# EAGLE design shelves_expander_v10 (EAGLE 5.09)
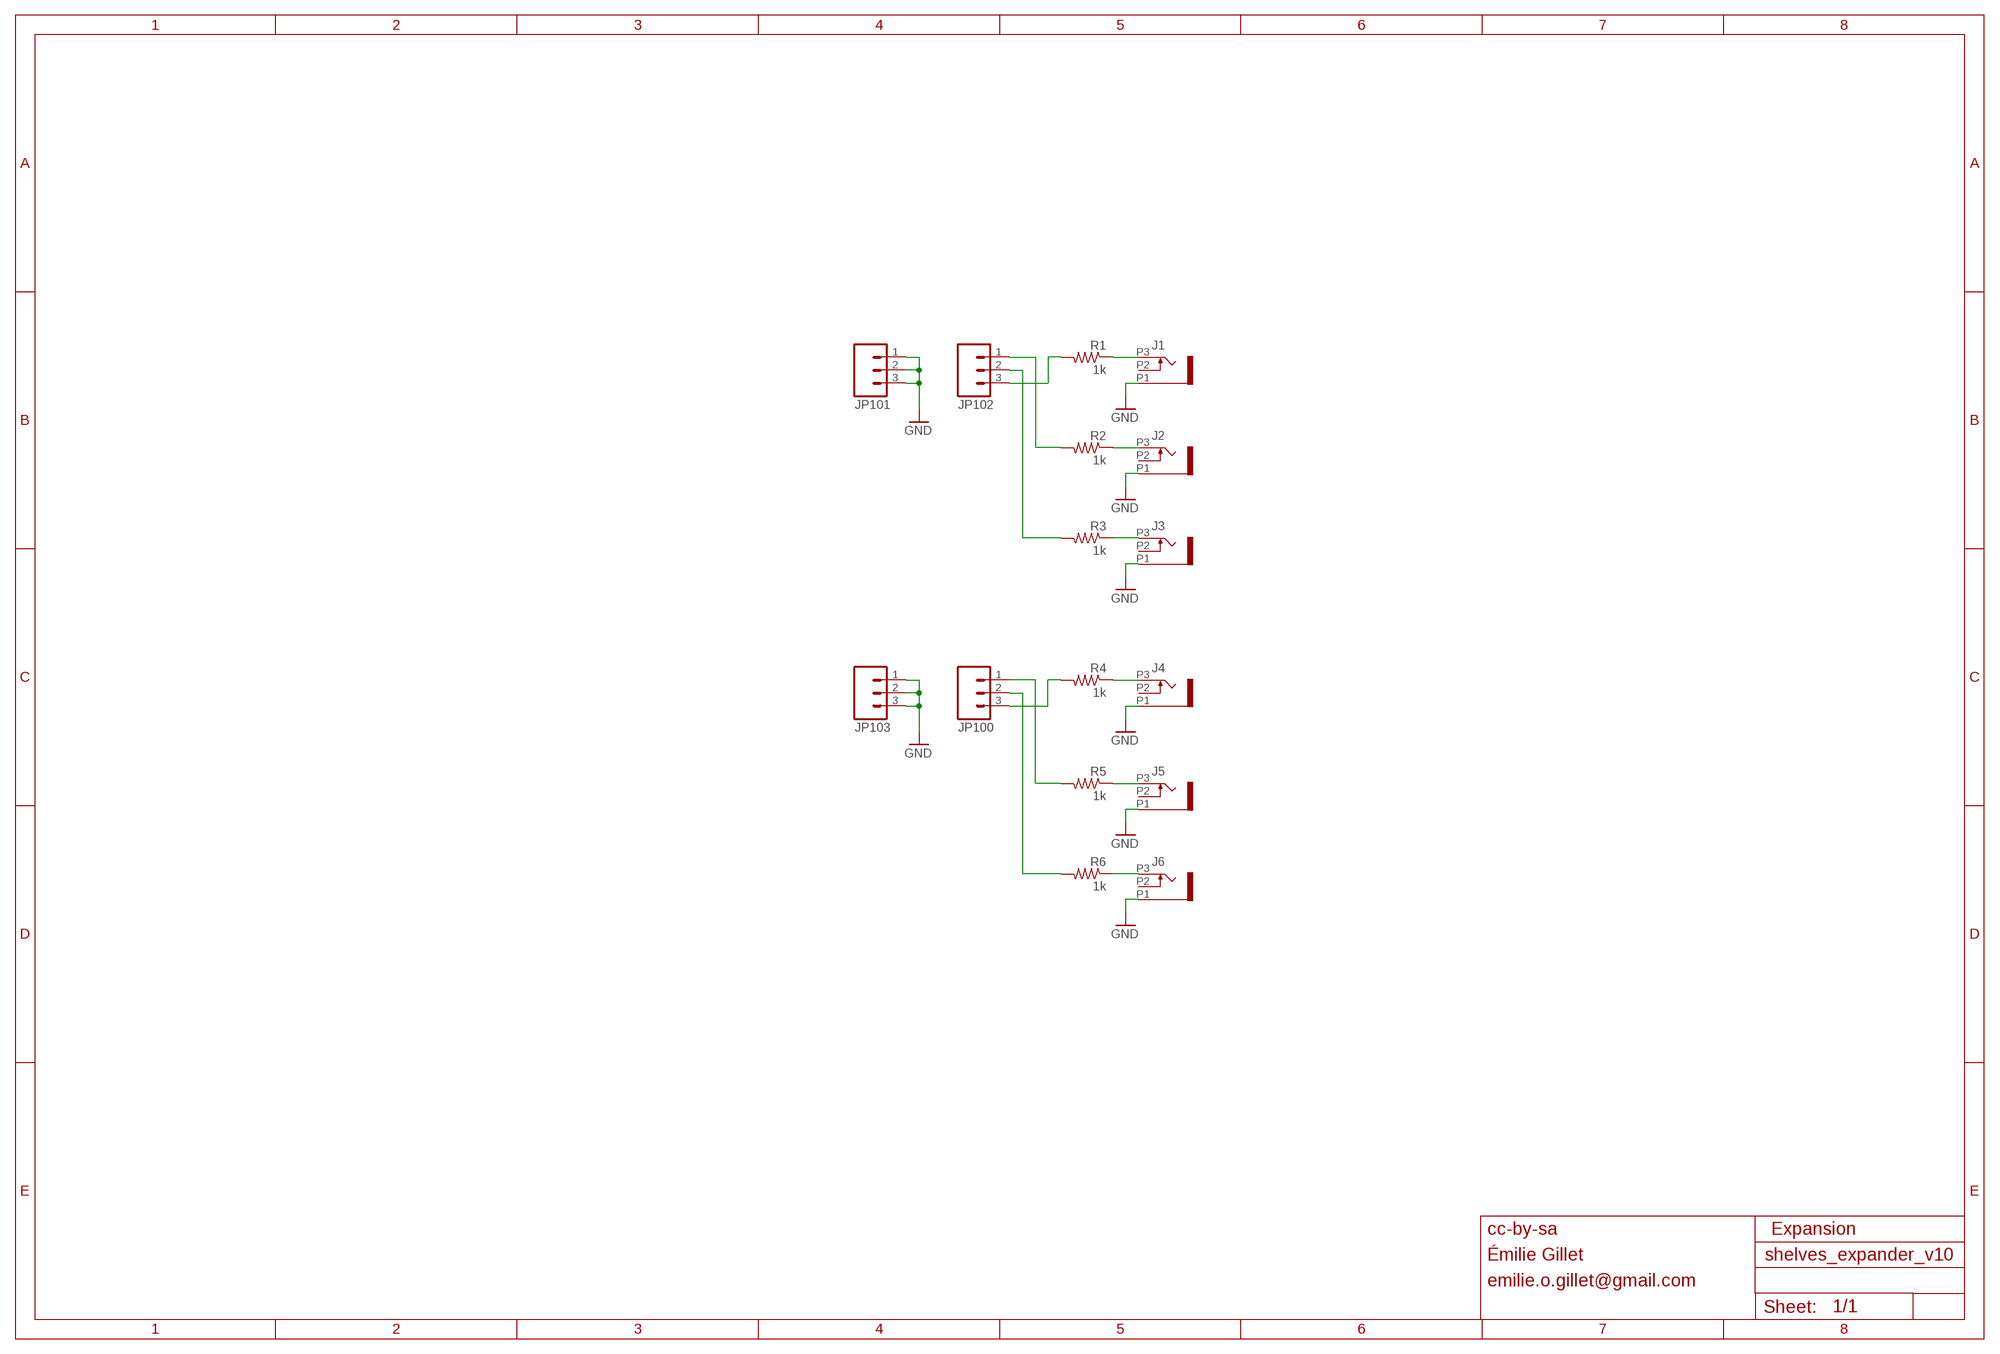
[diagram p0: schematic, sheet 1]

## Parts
J1  PJ301_THONKICONN6  [WQP_PJ_301M6]
J2  PJ301_THONKICONN6  [WQP_PJ_301M6]
J3  PJ301_THONKICONN6  [WQP_PJ_301M6]
J4  PJ301_THONKICONN6  [WQP_PJ_301M6]
J5  PJ301_THONKICONN6  [WQP_PJ_301M6]
J6  PJ301_THONKICONN6  [WQP_PJ_301M6]
JP100  M03PTH  [1X03]
JP101  M03PTH  [1X03]
JP102  M03PTH  [1X03]
JP103  M03PTH  [1X03]
R1  1k  R-US_R0603  [R0603]
R2  1k  R-US_R0603  [R0603]
R3  1k  R-US_R0603  [R0603]
R4  1k  R-US_R0603  [R0603]
R5  1k  R-US_R0603  [R0603]
R6  1k  R-US_R0603  [R0603]

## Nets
BP_1: JP102.1 R2.2
BP_2: JP100.1 R5.2
GND: J1.P1 J2.P1 J3.P1 J4.P1 J5.P1 J6.P1 JP101.1 JP101.2 JP101.3 JP103.1 JP103.2 JP103.3
HP_1: JP102.3 R1.2
HP_2: JP100.3 R4.2
N$1: J4.P3 R4.1
N$2: J1.P3 R1.1
N$3: J6.P3 R6.1
N$4: J2.P3 R2.1
N$5: J5.P3 R5.1
N$6: J3.P3 R3.1
N$8: JP100.2 R6.2
N$9: JP102.2 R3.2
Unconnected: J1.P2 J2.P2 J3.P2 J4.P2 J5.P2 J6.P2

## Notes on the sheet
- cc-by-sa | Expansion
- Émilie Gillet
- emilie.o.gillet@gmail.com

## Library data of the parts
J1-J6 = og-pj301:PJ301_THONKICONN
JP100-JP103 = SparkFun:M03: Header 3 Standard 3-pin 0.1" header. Use with straight break away headers (SKU : PRT-00116), right angle break away headers (PRT-00553), swiss pins (PRT-00743), machine pins (PRT-00117), and female headers (PRT-00115). Molex polarized connector foot print use with SKU : PRT-08232 with associated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
R1-R6 = rcl:R-US_: RESISTOR, American symbol

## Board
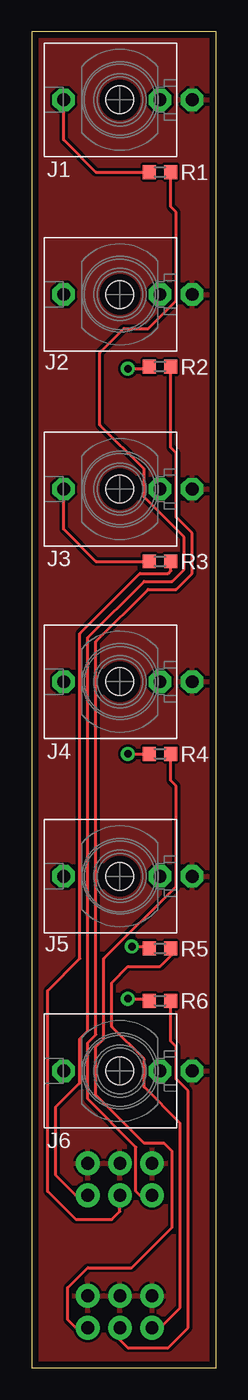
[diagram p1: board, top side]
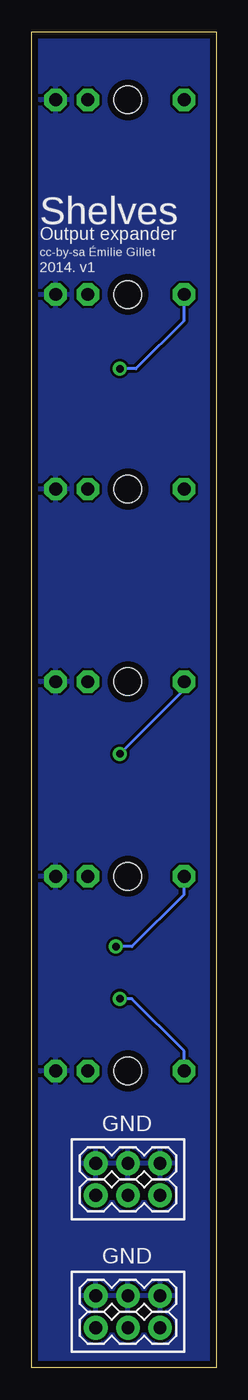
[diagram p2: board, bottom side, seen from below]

Size 14.61 x 105.73 mm. Coordinates in mm from the lower left corner, seen from the top.
Outline: 0,0 14.61,0 14.61,105.73 0,105.73 0,0
Copper layers (1*16): Top 0.035mm / dielectric 1.5mm / Bottom 0.035mm
Design rules "PCBCart-Standard": minimum track width 8mil, minimum drill 0.4mm, track to track 8mil, track to pad 8mil, pad to pad 8mil, via to via 8mil, smd to smd 8mil, copper to edge 20mil, drill to drill 8mil, minimum pad ring 8mil, minimum via ring 10mil, stop-mask expansion 3mil, vias tented up to drill 25mil, thermal gap 8mil

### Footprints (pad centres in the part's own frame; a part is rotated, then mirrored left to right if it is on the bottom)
WQP_PJ_301M6 = drill 1.016 pad 1.778 octagon: P1 0,-5.715; P2 0,-3.175; P3 0,4.445 | hole 2.2: 0,0
1X03 = drill 1.016 pad 1.88 round: 1 0,0; 2 2.54,0; 3 5.08,0
R0603 = smd 1 x 1.1: 1 -0.85,0; 2 0.85,0

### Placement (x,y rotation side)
J1  6.99,100.33 90 top
J2  6.99,84.93 90 top
J3  6.99,69.53 90 top
J4  6.99,54.29 90 top
J5  6.99,38.89 90 top
J6  6.99,23.5 90 top
JP100  9.53,3.17 0 bottom
JP101  9.53,5.71 0 bottom
JP102  9.53,13.65 0 bottom
JP103  9.53,16.19 0 bottom
R1  10.16,94.61 0 top
R2  10.16,79.22 0 top
R3  10.16,63.82 0 top
R4  10.16,48.58 0 top
R5  10.16,33.18 0 top
R6  10.16,29.05 0 top

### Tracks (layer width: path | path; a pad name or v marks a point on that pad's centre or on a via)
BP_1
  Top 0.254: JP102.1 8.57,13.65 8.26,13.97 8.26,17.46 4.45,21.27 4.45,25.72 5.08,26.35 5.08,57.47 9.21,61.59 11.43,61.59 12.7,62.87 12.7,66.04 11.43,67.31 11.43,72.39 11.01,72.81 R2.2
BP_2
  Top 0.254: JP100.1 10.16,3.17 11.75,4.76 11.75,19.37 8.89,22.23 8.89,24.45 6.35,26.99 6.35,30.48 7.62,31.75 10.16,31.75 11.01,32.6 R5.2
GND
  pour Bottom: 0,105.73 0,0 14.61,0 14.61,105.73
  pour Top (isolate 0.203): 0,105.73 0,0 14.61,0 14.61,105.73
HP_1
  Top 0.254: JP102.3 3.49,13.65 1.91,15.24 1.91,20.64 3.81,22.54 3.81,26.04 4.45,26.67 4.45,57.78 8.89,62.23 11.11,62.23 12.06,63.18 12.06,65.72 8.89,68.9 8.89,71.12 5.4,74.61 5.4,80.33 7.3,82.23 9.21,82.23 11.43,84.45 11.43,91.44 11.01,91.86 R1.2
HP_2
  Top 0.254: JP100.3 3.49,3.17 2.86,3.81 2.86,6.35 4.45,7.94 7.94,7.94 11.11,11.11 11.11,17.14 10.48,17.78 8.89,17.78 5.08,21.59 5.08,25.4 5.71,26.04 5.71,32.38 11.43,38.1 11.43,46.04 11.01,46.46 R4.2
N$1  (via drill 0.6)
  Top 0.254: v7.62,48.58 R4.1
  Bottom 0.254: v7.62,48.58 2.54,53.66 J4.P3
N$2
  Top 0.254: R1.1 5.08,94.61 2.54,97.16 J1.P3
N$3  (via drill 0.6)
  Top 0.254: R6.1 9.15,29.21 v7.62,29.21
  Bottom 0.254: v7.62,29.21 6.67,29.21 2.54,25.08 J6.P3
N$4  (via drill 0.6)
  Top 0.254: R2.1 9.15,79.06 v7.62,79.06
  Bottom 0.254: v7.62,79.06 6.35,79.06 2.54,82.87 J2.P3
N$5  (via drill 0.6)
  Top 0.254: R5.1 9.15,33.34 v7.94,33.34
  Bottom 0.254: v7.94,33.34 6.67,33.34 2.54,37.47 J5.P3
N$6
  Top 0.254: R3.1 5.08,63.82 2.54,66.36 J3.P3
N$8
  Top 0.254: JP100.2 6.99,2.22 7.62,1.59 10.79,1.59 12.38,3.17 12.38,21.91 11.43,22.86 11.43,25.4 11.01,25.82 R6.2
N$9
  Top 0.254: JP102.2 6.99,12.38 6.35,11.75 3.49,11.75 1.27,13.97 1.27,29.84 3.81,32.38 3.81,58.1 8.57,62.87 10.79,62.87 11.01,63.08 R3.2

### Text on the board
bNames: Shelves | Output expander | cc-by-sa Émilie Gillet | 2014. v1 | GND | GND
